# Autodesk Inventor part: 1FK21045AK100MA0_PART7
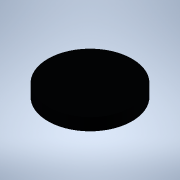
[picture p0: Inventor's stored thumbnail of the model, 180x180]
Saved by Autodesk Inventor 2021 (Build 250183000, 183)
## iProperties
Created: 2025-04
Part Number: 1FK21045AK100MA0_PART7
Material: Generic
Catalog Web Link: www.3dfindit.com
Description: -Servo synchronous motor
Document SubType Name: Modeling
Designer: psAdmin
Mass: 0.299142 g
Surface Area: 3.8585 cm^2
Volume: 0.299142 cm^3
Density: 1 g/cm^3
Appearance: PSOLRGB-38-46-56
Category: PARTsolutions
Title: 1FK21045AK100MA0_PART7
Author: Cadenas PARTsolutions
Comments: Servo synchronous motor
Sending System: PARTsolutions
Preprocessor: ST-DEVELOPER v19.3
PSOL_IDENT_0: {$CADENAS_DATA/23d-libs/siemens_ag/_cat_/e0/5f/1fk21045ak100ma0.prj},213 {VTYP=3D},{NB=1FK21045AK100
PSOL_IDENT_1: MA0_PART7},{LINA=1FK21045AK100MA0_PART7},{NN=1FK21045AK100MA0_PART7},{NOPRJ=TRUE},{DATE=19.08.2025 1
PSOL_IDENT_2: 4:01:03},{GEOMDATE=30.07.2025 02:01:57},{VERSION=},{LINEID=10},{WBVAR=},{WBNUMERIC=}  {NB=1FK21045AK
PSOL_IDENT_3: 100MA0_PART7},{LINA=1FK21045AK100MA0_PART7},{KT=DUMMY},{PREVIEW=../../../_pool_/0f/2c/p_d211_xx_0043
PSOL_IDENT_4: 8j.png},{DESCSHORT=SIMOTICS S-1FK2 HD, SINAMICS S210 3AC 400V-480V, 1.7 Nm, 6000 rpm},{DESCLONG=SIMO
PSOL_IDENT_5: TICS S-1FK2 HD servo motor M0=2.4 Nm; PN = 1.07 kW at nN=6000 rpm (380-480 V); PN = 0.75 kW at nN=30
PSOL_IDENT_6: 00 rpm (200-240 V); with holding brake; degree of protection IP64; cylindrical shaft D19x40mm; absol
PSOL_IDENT_7: ute encoder 22-bit + 12-bit multiturn (encoder AM22DQC); with OCC interface; plug size M17, rotatabl
PSOL_IDENT_8: e; SIMOTICS S-1FK2 servomotorfor a wide range of uses in industrial environments. SIMOTICS S‑1FK2 se
PSOL_IDENT_9: rvomotors are compact synchronous motors with a high dynamic performance that set themselves apart a
PSOL_IDENT_10: s a result of their high power density, degree of protection and overload capability. The motors are
PSOL_IDENT_11: available in two variants: as High Dynamic variant (highest dynamic performance as a result of the
PSOL_IDENT_12: low intrinsic moment of inertia for applications demanding a high dynamic performance with low moved
PSOL_IDENT_13: masses) - and as Compact variant (precise and stable closed-loop control for medium up to large mov
PSOL_IDENT_14: ed masses as a result of a medium intrinsic moment of inertia). SIMOTICSS‑1FK2 servomotors fully exp
PSOL_IDENT_15: loit their strengths in a system with the SINAMICSS210 frequency converter and simple connection usi
PSOL_IDENT_16: ng the one cable connection (OCC). Advantages include the short control and positioning times, fast
PSOL_IDENT_17: and precise correction of disturbing quantities as well as stable control with a high dynamic perfor
PSOL_IDENT_18: mance. The servo motors can be configured to address a wide range of requirements. For example with
PSOL_IDENT_19: and without holding brake, IP64 or IP65 degree of protection, singleturn or multiturn absolute encod
PSOL_IDENT_20: ers - to name just a few. Further, the servomotors are available in different shaft heights extendin
PSOL_IDENT_21: g from 20 to 100. A shaft sealing ring is available to achieve an IP65 degree of protection and for
PSOL_IDENT_22: subsequent mounting at the motor or as spare part. SIMOTICS - the optimum motor for each and every m
PSOL_IDENT_23: otion control application.},{INTNO=804766807114},{SUPPLIERALTNO=1FK2104-5AK10-0MA0},{MANUID=1FK21045
PSOL_IDENT_24: AK100MA0},{MANUNAME=Siemens},{MANUTYPEDESC=Synchronous motor 1FK2-HD 2,39 Nm},{AAU732=SIMOTICS},{AAO
PSOL_IDENT_25: 057=S-1FK2},{AAU734=SIMOTICS S-1FK2 HD servo motor M0=2.4 Nm; PN = 1.07 kW at nN=6000 rpm (380-480 V
PSOL_IDENT_26: ); PN = 0.75 kW at nN=3000 rpm (200-240 V); with holding brake; degree of protection IP64; cylindric
PSOL_IDENT_27: al shaft D19x40mm; absolute encoder 22-bit + 12-bit multiturn (encoder AM22DQC); with OCC interface;
PSOL_IDENT_28: plug size M17, rotatable;},{AAW338=Synchronous motor 1FK2-HD 2,39 Nm},{AAO742=SIMOTICS},{AAO663=404
PSOL_IDENT_29: 2948691236},{NOCUPEROU=1},{PRICEQUANTITY=1},{QUANTITYMIN=1},{QUANTITYINT=1},{CTN=85015100},{COO=DE},
PSOL_IDENT_30: {AAO676=1FK2104-5AK10-0MA0},{AAO677=Siemens AG},{ORDERUNIT=C62},{CONTENTUNIT=C62}
NB: 1FK21045AK100MA0_PART7
NT: Servo synchronous motor
NBSYN: $MANUID._PART7
LINA: 1FK21045AK100MA0_PART7
CATALOG: SIEMENS
PREVIEW: ../../../_pool_/0f/2c/p_d211_xx_00438j.png
DESCSHORT: SIMOTICS S-1FK2 HD, SINAMICS S210 3AC 400V-480V, 1.7 Nm, 6000 rpm
DESCLONG: SIMOTICS S-1FK2 HD servo motor M0=2.4 Nm; PN = 1.07 kW at nN=6000 rpm (380-480 V); PN = 0.75 kW at nN=3000 rpm (200-240 V); with holding brake; degree of protec
INTNO: 804766807114
SUPPLIERALTNO: 1FK2104-5AK10-0MA0
MANUID: 1FK21045AK100MA0
MANUNAME: Siemens
MANUTYPEDESC: Synchronous motor 1FK2-HD 2,39 Nm
AAU732: SIMOTICS
AAO057: S-1FK2
AAU734: SIMOTICS S-1FK2 HD servo motor M0=2.4 Nm; PN = 1.07 kW at nN=6000 rpm (380-480 V); PN = 0.75 kW at nN=3000 rpm (200-240 V); with holding brake; degree of protec
AAW338: Synchronous motor 1FK2-HD 2,39 Nm
AAO742: SIMOTICS
AAO663: 4042948691236.0
NOCUPEROU: 1
PRICEQUANTITY: 1
QUANTITYMIN: 1
QUANTITYINT: 1
CTN: 85015100
COO: DE
ARTICLENO: 1FK21045AK100MA0_PART7
BOMINFO: 1FK21045AK100MA0_PART7
CREATOR: CADENAS GmbH
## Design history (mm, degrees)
feature "2025_04_17_15_45_15_0086"
body "Solid1"
